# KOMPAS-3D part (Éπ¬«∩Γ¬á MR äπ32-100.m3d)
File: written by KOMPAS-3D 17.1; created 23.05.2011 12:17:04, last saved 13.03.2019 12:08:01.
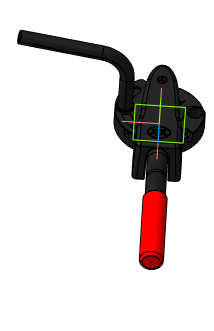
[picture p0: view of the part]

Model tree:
1. Плоскость XY
2. Плоскость ZX
3. Плоскость ZY
4. Ось X
5. Ось Y
6. Ось Z
7. Начало координат
8. Операция без истории:2

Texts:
  Viktor2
